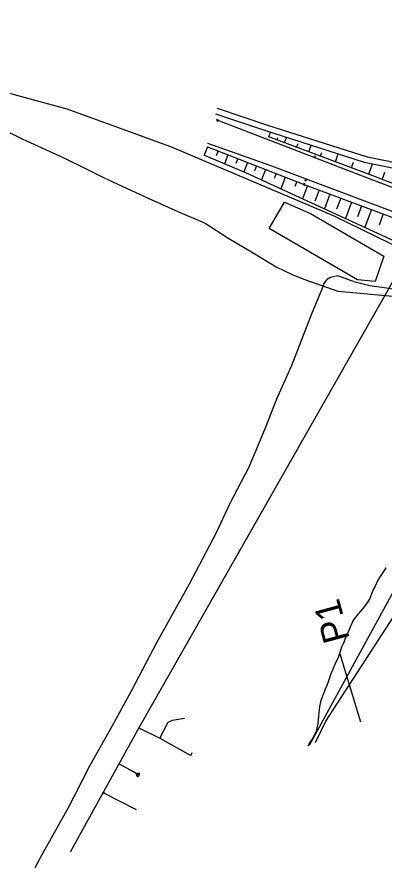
# Model space of a CAD drawing. Extents: x -737422 to -734235, y -1145631 to -1142623.
# Drawn here: x -736073.2 to -735933.5, y -1144115.7 to -1143792.7 of the extents above; entities that cross this region are included whole.
import ezdxf

# ---------------------------------------------------------------- set-up
doc = ezdxf.new("R2010")
doc.units = 0
for name, color, linetype in [('Vrstva 1', 7, 'Continuous'), ('Vrstva 19', 7, 'Continuous'), ('Vrstva 20', 7, 'Continuous'), ('Vrstva 21', 7, 'Continuous'), ('Vrstva 26', 7, 'Continuous'), ('Vrstva 29', 7, 'Continuous'), ('Vrstva 30', 7, 'Continuous'), ('Vrstva 8', 7, 'Continuous'), ('Vrstva 9', 7, 'Continuous')]:
    doc.layers.add(name, color=color, linetype=linetype)

# ---------------------------------------------------------------- blocks, each defined once
blk = doc.blocks.new('6.140')
at = {"layer": 'Vrstva 1'}
blk.add_circle((0, 0), 0.5, dxfattribs=at)
blk = doc.blocks.new('6.111')
at = {"layer": 'Vrstva 1'}
blk.add_line((0, -2), (0, -1), dxfattribs=at)
blk.add_lwpolyline([(-1, 0), (-1, 1), (1, 1), (1, 0)], dxfattribs=at)
blk.add_lwpolyline([(-1, -1), (1, -1), (1, 0), (-1, 0)], close=True, dxfattribs=at)

msp = doc.modelspace()

# ---------------------------------------------------------------- linework, layer by layer
at = {"layer": 'Vrstva 1'}
for points in [[(-736110.24, -1143822.83), (-736101.14, -1143824.79), (-736093.04, -1143828.13), (-736083.5, -1143832.85), (-736070.97, -1143838.98), (-736056.88, -1143845.51), (-736049.44, -1143848.98), (-736040.33, -1143853.59), (-736031.38, -1143857.81), (-736021.98, -1143862.09), (-736012.17, -1143866.45), (-736001.78, -1143870.93), (-735992.84, -1143876.77), (-735983.53, -1143882.19), (-735974.85, -1143887.45), (-735968.55, -1143890.48), (-735961.63, -1143893.24)], [(-735924.85, -1143896.79), (-735939.32, -1143894.69), (-735944.86, -1143893.37), (-735951.44, -1143890.91), (-735954.15, -1143891.5), (-735955.67, -1143892.45), (-735956.8, -1143893.78), (-735957.63, -1143896.36), (-735961.27, -1143905.14), (-735969.15, -1143925.31), (-735972.06, -1143931.81), (-735974.68, -1143937.74), (-735978.96, -1143948.75), (-735985.21, -1143963.49), (-735992.46, -1143977.36), (-735997.64, -1143988.49), (-736007.92, -1144008.02), (-736020.23, -1144030.27), (-736029.94, -1144048.59), (-736037.24, -1144061.94), (-736045.53, -1144076.84), (-736051.63, -1144088.65), (-736053.82, -1144092.93), (-736063.75, -1144110.76), (-736066.481, -1144115.707)], [(-735886.76, -1143905.49), (-735889.14, -1143903.75), (-735904.2, -1143901.22), (-735951.34, -1143896.9), (-735961.63, -1143893.24)], [(-735933.225, -1144001.824), (-735933.562, -1144002.408), (-735935.562, -1144005.408), (-735935.954, -1144006.016), (-735936.338, -1144006.711)], [(-735936.338, -1144006.711), (-735937.296, -1144008.674), (-735937.979, -1144009.991), (-735938.309, -1144010.741), (-735939.335, -1144013.355), (-735939.76, -1144014.21), (-735940.144, -1144014.825), (-735941.389, -1144016.581), (-735944.155, -1144019.815), (-735944.622, -1144020.427), (-735945.42, -1144021.549), (-735945.809, -1144022.161), (-735946.174, -1144022.875), (-735946.496, -1144023.632), (-735947.196, -1144025.494), (-735947.571, -1144026.399), (-735948.22, -1144027.75), (-735949.398, -1144030.572), (-735950.029, -1144031.941), (-735950.331, -1144032.718), (-735951.233, -1144035.457), (-735951.588, -1144036.382), (-735952.269, -1144037.859), (-735953.391, -1144040.579), (-735954.025, -1144041.945), (-735954.329, -1144042.721), (-735955.231, -1144045.458), (-735955.583, -1144046.387), (-735956.201, -1144047.769), (-735956.51, -1144048.539), (-735957.835, -1144052.135), (-735958.126, -1144053.23), (-735958.341, -1144054.401), (-735958.504, -1144055.624), (-735958.878, -1144059.469), (-735959.023, -1144060.729), (-735959.212, -1144061.946), (-735959.468, -1144063.096), (-735959.819, -1144064.151), (-735960.138, -1144064.832), (-735960.544, -1144065.584), (-735961.217, -1144066.753), (-735962.01, -1144067.96), (-735962.879, -1144069.439)]]:
    msp.add_lwpolyline(points, dxfattribs=at)
at = {"layer": 'Vrstva 19'}
for points in [[(-736018.98, -1144066.39), (-736015.79, -1144060.36), (-736014.23, -1144059.53), (-736009.67, -1144058.89)], [(-736027.01, -1144062.46), (-736018.98, -1144066.39)], [(-736018.98, -1144066.39), (-736007.29, -1144072.96), (-736006.71, -1144071.91)], [(-736027.4, -1144080.18), (-736030.08, -1144078.52), (-736034.54, -1144076.11)], [(-736040.62, -1144087.13), (-736040.44, -1144087.22), (-736027.95, -1144093.54)]]:
    msp.add_lwpolyline(points, dxfattribs=at)
at = {"layer": 'Vrstva 20'}
for points in [[(-735926.33, -1143881.23), (-735953.05, -1143868.15), (-736014.79, -1143841.91), (-736054.2, -1143827.69), (-736085.89, -1143819.04), (-736119.02, -1143815.95), (-736125.21, -1143815.29), (-736125.14, -1143814.39), (-736123.55, -1143792.66)], [(-735997.81, -1143829.47), (-735979.28, -1143835.63)], [(-735997.19, -1143827.3), (-735978.07, -1143833.68)], [(-735997.31, -1143831.53), (-735997.48, -1143832)], [(-735997.48, -1143832), (-735997.01, -1143832.17)], [(-735997.4, -1143831.76), (-735996.93, -1143831.94)], [(-735996.84, -1143831.7), (-735997.31, -1143831.53)], [(-735936.1, -1143855.36), (-735997.19, -1143831.85)], [(-735997.01, -1143832.17), (-735996.84, -1143831.7)], [(-735979.28, -1143835.63), (-735941.43, -1143847.79)], [(-735978.07, -1143833.68), (-735940.27, -1143845.8)], [(-735935.06, -1143854.03), (-735977.68, -1143838.19)], [(-736000.93, -1143841.91), (-735964.17, -1143856.22)], [(-735977.47, -1143848.86), (-736000.8, -1143840.72)], [(-736002.43, -1143844.99), (-735986.51, -1143851.72)], [(-735960.41, -1143845.47), (-735960.58, -1143845.94)], [(-735960.58, -1143845.94), (-735960.11, -1143846.11)], [(-735960.5, -1143845.7), (-735960.03, -1143845.88)], [(-735959.94, -1143845.64), (-735960.41, -1143845.47)], [(-735960.11, -1143846.11), (-735959.94, -1143845.64)], [(-735940.27, -1143845.8), (-735905.76, -1143852.73)], [(-735903.83, -1143876.63), (-735977.47, -1143848.86)], [(-735941.43, -1143847.79), (-735906.84, -1143854.69)], [(-735986.51, -1143851.72), (-735906.67, -1143888.33)], [(-735963.83, -1143854.25), (-735964, -1143854.72)], [(-735964, -1143854.72), (-735963.53, -1143854.89)], [(-735963.92, -1143854.48), (-735963.45, -1143854.66)], [(-735963.36, -1143854.42), (-735963.83, -1143854.25)], [(-735963.53, -1143854.89), (-735963.36, -1143854.42)], [(-735895.93, -1143870.45), (-735936.1, -1143855.36)], [(-735935.06, -1143854.03), (-735895.2, -1143868.58)], [(-735964.29, -1143855.9), (-735964.46, -1143856.37)], [(-735964.46, -1143856.37), (-735963.99, -1143856.54)], [(-735964.38, -1143856.13), (-735963.91, -1143856.31)], [(-735963.82, -1143856.07), (-735964.29, -1143855.9)], [(-735964.17, -1143856.22), (-735904.49, -1143878.47)], [(-735963.99, -1143856.54), (-735963.82, -1143856.07)], [(-735977.46, -1143872.91), (-735971.67, -1143862.97)], [(-735971.67, -1143862.97), (-735961.85, -1143867.24)], [(-735961.85, -1143867.24), (-735934, -1143883.47)], [(-735943.98, -1143892.42), (-735977.46, -1143872.91)], [(-735934, -1143883.47), (-735937.27, -1143893.12)], [(-735926.67, -1143885.3), (-735927.12, -1143886.18), (-735931.12, -1143894.02), (-735931.41, -1143894.59), (-736027.01, -1144062.46), (-736053.093, -1144109.728)], [(-735937.27, -1143893.12), (-735943.98, -1143892.42)]]:
    msp.add_lwpolyline(points, dxfattribs=at)
at = {"layer": 'Vrstva 21'}
for points in [[(-735977.68, -1143838.19), (-735977.03, -1143836.35)], [(-735974.54, -1143839.35), (-735974.22, -1143838.45)], [(-735971.66, -1143840.43), (-735970.93, -1143838.36)], [(-736000.93, -1143841.91), (-736002.17, -1143845.1)], [(-735967.06, -1143842.14), (-735966.53, -1143840.68)], [(-735962.45, -1143843.85), (-735961.54, -1143841.33)], [(-735996.89, -1143843.48), (-735997.64, -1143845.42)], [(-735993.16, -1143844.93), (-735994.48, -1143848.35)], [(-735957.96, -1143845.52), (-735957.46, -1143844.12)], [(-735952.34, -1143847.61), (-735951.26, -1143844.63)], [(-735989.43, -1143846.39), (-735990.18, -1143848.33)], [(-735985.7, -1143847.84), (-735987.11, -1143851.47)], [(-735982.28, -1143849.17), (-735983.03, -1143851.11)], [(-735946.25, -1143849.87), (-735945.52, -1143847.82)], [(-735939.71, -1143852.3), (-735938.31, -1143848.41)], [(-735978.86, -1143850.5), (-735980.42, -1143854.51)], [(-735974.82, -1143852.07), (-735975.57, -1143854.02)], [(-735934.62, -1143854.37), (-735933.59, -1143851.52)], [(-735971.39, -1143853.41), (-735973.13, -1143857.85)], [(-735967.04, -1143855.1), (-735967.8, -1143857.04)], [(-735963, -1143856.67), (-735964.85, -1143861.65)], [(-735958.54, -1143858.33), (-735960.12, -1143862.56)], [(-735954.43, -1143859.87), (-735956.52, -1143865.47)], [(-735950.32, -1143861.4), (-735951.89, -1143865.63)], [(-735946.2, -1143862.93), (-735948.51, -1143869.14)], [(-735942.43, -1143864.34), (-735944.01, -1143868.57)], [(-735938.66, -1143865.74), (-735941.18, -1143872.5)], [(-735934.2, -1143867.4), (-735935.78, -1143871.63)]]:
    msp.add_lwpolyline(points, dxfattribs=at)
at = {"layer": 'Vrstva 30'}
for points in [[(-735959.949, -1144068.13), (-735956, -1144060), (-735930, -1144020), (-735908, -1143979), (-735884, -1143931), (-735875, -1143917), (-735872, -1143913)], [(-735925.19, -1144001.43), (-735962.274, -1144069.168)]]:
    msp.add_lwpolyline(points, dxfattribs=at)
at = {"layer": 'Vrstva 8'}
msp.add_lwpolyline([(-735942.666, -1144060.411), (-735950.52, -1144034.5)], dxfattribs=at)

# ---------------------------------------------------------------- block references
at = {"layer": 'Vrstva 26', "xscale": 0.5, "yscale": 0.5}
msp.add_blockref('6.140', (-736040.44, -1144087.22), dxfattribs=at)
at = {"layer": 'Vrstva 29', "xscale": 0.5, "yscale": 0.5}
msp.add_blockref('6.111', (-736027.4, -1144080.18), dxfattribs=at)

# ---------------------------------------------------------------- texts
at = {"layer": 'Vrstva 9'}
msp.add_text('P1', height=10, rotation=105.227, dxfattribs=at).set_placement((-735946.84, -1144028.71))

doc.saveas('drawing.dxf')
